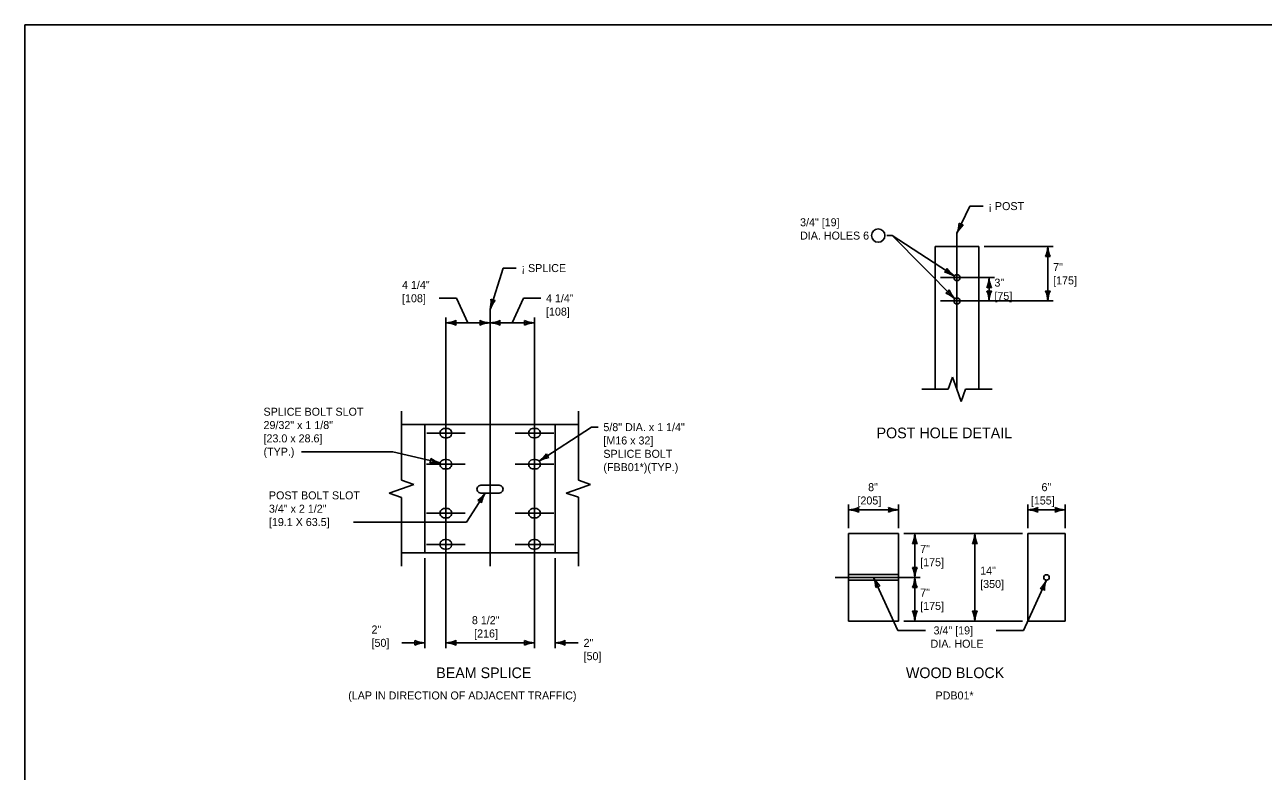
# Model space of a CAD drawing. Extents: x 49991.4 to 50021, y 49987.6 to 50011.4.
# Drawn here: x 49999.38 to 50008.67, y 49993.4 to 49999 of the extents above; entities that cross this region are included whole.
import ezdxf

# ---------------------------------------------------------------- set-up
doc = ezdxf.new("R2010")
doc.units = 0
for name, color, linetype in [('Level 1', 7, 'Continuous'), ('Level 2', 7, 'Continuous'), ('Level 3', 7, 'Continuous'), ('Level 4', 7, 'Continuous'), ('Level 5', 7, 'Continuous'), ('Level 6', 7, 'Continuous')]:
    doc.layers.add(name, color=color, linetype=linetype)

msp = doc.modelspace()

# ---------------------------------------------------------------- linework, layer by layer
at = {"layer": 'Level 1'}
for p, q in [((50006.209, 49997.3355), (50006.5371, 49997.3355)), ((50006.209, 49997.3355), (50006.209, 49996.2646)), ((50006.5371, 49997.3355), (50006.5371, 49996.2646)), ((50002.2084, 49995.9992), (50003.5353, 49995.9992)), ((50002.3835, 49995.0379), (50002.3835, 49995.9992)), ((50002.5496, 49995.9713), (50002.5326, 49995.9713)), ((50003.214, 49995.9714), (50003.197, 49995.9714)), ((50002.5496, 49995.9005), (50002.5326, 49995.9005)), ((50003.214, 49995.9006), (50003.197, 49995.9006)), ((50002.5495, 49995.7374), (50002.5325, 49995.7374)), ((50003.214, 49995.7374), (50003.197, 49995.7374)), ((50002.5495, 49995.6666), (50002.5325, 49995.6666)), ((50003.214, 49995.6666), (50003.197, 49995.6666)), ((50002.9403, 49995.5443), (50002.8036, 49995.5443)), ((50002.8036, 49995.4857), (50002.9403, 49995.4857)), ((50002.5495, 49995.3705), (50002.5325, 49995.3705)), ((50003.214, 49995.3705), (50003.197, 49995.3705)), ((50002.5495, 49995.2997), (50002.5325, 49995.2997)), ((50003.214, 49995.2997), (50003.197, 49995.2997)), ((50005.561, 49995.1822), (50005.9359, 49995.1822)), ((50005.561, 49995.1822), (50005.561, 49994.5256)), ((50005.9359, 49995.1822), (50005.9359, 49994.5256)), ((50006.9039, 49995.1822), (50006.9039, 49994.5256)), ((50006.9039, 49995.1822), (50007.1852, 49995.1822)), ((50007.1852, 49995.1822), (50007.1852, 49994.5256)), ((50002.5495, 49995.1366), (50002.5325, 49995.1366)), ((50003.214, 49995.1366), (50003.197, 49995.1366)), ((50002.2084, 49995.0379), (50003.5353, 49995.0379)), ((50002.5495, 49995.0658), (50002.5325, 49995.0658)), ((50003.214, 49995.0658), (50003.197, 49995.0658)), ((50005.561, 49994.5256), (50005.9359, 49994.5256)), ((50007.1852, 49994.5256), (50006.9039, 49994.5256))]:
    msp.add_line(p, q, dxfattribs=at)
msp.add_lwpolyline([(49999.3835, 49998.9992), (50016.7501, 49998.9992), (50016.7501, 49987.7988), (49999.3835, 49987.7988)], close=True, dxfattribs=at)
for centre, radius in [((50006.3731, 49997.1022), 0.0237), ((50006.3731, 49996.9272), 0.0237), ((50007.0448, 49994.8529), 0.0205)]:
    msp.add_circle(centre, radius, dxfattribs=at)
for centre, major_axis, ratio, start_param, end_param in [((50002.5326, 49995.9359), (0.0354, 0), 0.998676, 1.570796, 4.712389), ((50002.5496, 49995.9359), (0.0354, 0), 0.998676, 4.712389, 7.853982), ((50003.197, 49995.936), (0.0354, 0), 0.998676, 1.570796, 4.712389), ((50003.214, 49995.936), (0.0354, 0), 0.998676, 4.712389, 7.853982), ((50002.5325, 49995.702), (0.0354, 0), 0.998676, 1.570796, 4.712389), ((50002.5495, 49995.702), (0.0354, 0), 0.998676, 4.712389, 7.853982), ((50003.197, 49995.702), (0.0354, 0), 0.998676, 1.570796, 4.712389), ((50003.214, 49995.702), (0.0354, 0), 0.998676, 4.712389, 7.853982), ((50002.8036, 49995.515), (0.0296, 0), 0.988923, 1.570796, 4.712389), ((50002.9403, 49995.515), (0.0294, 0), 0.995211, 4.712389, 7.853982), ((50002.5325, 49995.3351), (0.0354, 0), 0.998676, 1.570796, 4.712389), ((50002.5495, 49995.3351), (0.0354, 0), 0.998676, 4.712389, 7.853982), ((50003.197, 49995.3351), (0.0354, 0), 0.998676, 1.570796, 4.712389), ((50003.214, 49995.3351), (0.0354, 0), 0.998676, 4.712389, 7.853982), ((50002.5325, 49995.1012), (0.0354, 0), 0.998676, 1.570796, 4.712389), ((50002.5495, 49995.1012), (0.0354, 0), 0.998676, 4.712389, 7.853982), ((50003.197, 49995.1012), (0.0354, 0), 0.998676, 1.570796, 4.712389), ((50003.214, 49995.1012), (0.0354, 0), 0.998676, 4.712389, 7.853982)]:
    msp.add_ellipse(centre, major_axis=major_axis, ratio=ratio, start_param=start_param, end_param=end_param, dxfattribs=at)
at = {"layer": 'Level 2'}
msp.add_circle((50005.7832, 49997.4175), 0.05, dxfattribs=at)
at = {"layer": 'Level 3'}
for p, q in [((50006.3731, 49997.4355), (50006.4709, 49997.6387)), ((50006.4709, 49997.6387), (50006.5692, 49997.6387)), ((50005.8467, 49997.4175), (50005.8867, 49997.4175)), ((50005.8867, 49997.4175), (50006.3564, 49996.944)), ((50005.8867, 49997.4175), (50006.3532, 49997.1151)), ((50006.5771, 49997.3355), (50007.0946, 49997.3355)), ((50007.0546, 49997.3355), (50007.0546, 49996.9272)), ((50002.872, 49996.8632), (50002.9698, 49997.1738)), ((50002.9698, 49997.1738), (50003.0681, 49997.1738)), ((50006.6143, 49997.1022), (50006.6143, 49996.9272)), ((50002.5411, 49996.7632), (50002.872, 49996.7632)), ((50003.2055, 49996.7632), (50002.872, 49996.7632)), ((50003.6342, 49995.9804), (50003.2409, 49995.725)), ((50003.6822, 49995.9804), (50003.6342, 49995.9804)), ((50002.143, 49995.7961), (50001.4574, 49995.7961)), ((50002.4985, 49995.7121), (50002.143, 49995.7961)), ((50002.6959, 49995.2685), (50002.835, 49995.4857)), ((50005.561, 49995.4002), (50005.561, 49995.2222)), ((50005.561, 49995.3602), (50005.9359, 49995.3602)), ((50005.9359, 49995.4002), (50005.9359, 49995.2222)), ((50006.9039, 49995.4002), (50006.9039, 49995.2222)), ((50006.9039, 49995.3602), (50007.1854, 49995.3602)), ((50007.1854, 49995.4002), (50007.1854, 49995.2222)), ((50001.848, 49995.2685), (50002.6959, 49995.2685)), ((50005.9759, 49995.1822), (50006.8639, 49995.1822)), ((50006.0577, 49995.1822), (50006.0577, 49994.8526)), ((50006.5075, 49995.1822), (50006.5075, 49994.5256)), ((50002.3835, 49994.9979), (50002.3835, 49994.3223)), ((50003.3602, 49994.9979), (50003.3602, 49994.3223)), ((50005.9289, 49994.4556), (50005.7484, 49994.8526)), ((50006.0577, 49994.8526), (50006.0577, 49994.5256)), ((50006.8735, 49994.4556), (50007.0448, 49994.8323)), ((50005.9759, 49994.5256), (50006.8639, 49994.5256)), ((50006.137, 49994.4556), (50005.9289, 49994.4556)), ((50006.6672, 49994.4556), (50006.8735, 49994.4556)), ((50002.2101, 49994.3623), (50002.3835, 49994.3623)), ((50002.5411, 49994.3623), (50003.2055, 49994.3623)), ((50003.5336, 49994.3623), (50003.3602, 49994.3623))]:
    msp.add_line(p, q, dxfattribs=at)
for points in [[(50002.7066, 49996.7632), (50002.6198, 49996.9472), (50002.492, 49996.9472)], [(50003.0375, 49996.7632), (50003.1242, 49996.9472), (50003.252, 49996.9472)]]:
    msp.add_lwpolyline(points, dxfattribs=at)
for centre, radius, start, end in [((50006.1573, 49997.5234), 0.233, 337.82731, 357.07716), ((50006.5705, 49997.3333), 0.2223, 132.45601, 152.63952), ((50006.4272, 49997.5517), 0.0548, 227.13882, 262.86118), ((50006.8324, 49997.3447), 0.2223, 337.45601, 357.63952), ((50007.2873, 49997.347), 0.233, 182.82731, 202.07716), ((50007.0546, 49997.2073), 0.0548, 72.13882, 107.86118), ((50006.2456, 49997.1849), 0.0548, 309.18565, 344.90801), ((50006.2362, 49996.9136), 0.233, 59.87414, 79.12399), ((50006.4817, 49997.2965), 0.2223, 214.50284, 234.68635), ((50006.3922, 49997.1114), 0.2223, 337.45601, 357.63952), ((50006.6143, 49996.974), 0.0548, 72.13882, 107.86118), ((50006.847, 49997.1137), 0.233, 182.82731, 202.07716), ((50002.6466, 49996.9221), 0.233, 345.34968, 4.59953), ((50002.9105, 49996.9855), 0.0548, 234.66119, 270.38355), ((50006.2661, 49997.035), 0.0548, 296.90501, 332.62737), ((50006.1992, 49996.772), 0.233, 47.5935, 66.84335), ((50006.5205, 49997.0939), 0.2223, 202.2222, 222.40571), ((50006.6143, 49997.0554), 0.0548, 252.13882, 287.86118), ((50006.3816, 49996.9157), 0.233, 2.82731, 22.07716), ((50006.8364, 49996.918), 0.2223, 157.45601, 177.63952), ((50007.0546, 49997.0554), 0.0548, 252.13882, 287.86118), ((50006.8218, 49996.9157), 0.233, 2.82731, 22.07716), ((50007.2767, 49996.918), 0.2223, 157.45601, 177.63952), ((50003.0811, 49996.7878), 0.2223, 139.97838, 160.16189), ((50002.5296, 49996.9959), 0.233, 272.82731, 292.07716), ((50002.5319, 49996.5411), 0.2223, 67.45601, 87.63952), ((50002.6693, 49996.7632), 0.0548, 162.13882, 197.86118), ((50002.8812, 49996.9853), 0.2223, 247.45601, 267.63952), ((50002.7438, 49996.7632), 0.0548, 342.13882, 17.86118), ((50002.8835, 49996.5305), 0.233, 92.82731, 112.07716), ((50002.8605, 49996.9959), 0.233, 272.82731, 292.07716), ((50002.8628, 49996.5411), 0.2223, 67.45601, 87.63952), ((50003.0002, 49996.7632), 0.0548, 162.13882, 197.86118), ((50003.2147, 49996.9853), 0.2223, 247.45601, 267.63952), ((50003.0773, 49996.7632), 0.0548, 342.13882, 17.86118), ((50003.217, 49996.5305), 0.233, 92.82731, 112.07716), ((50002.3737, 49995.7416), 0.0548, 328.83975, 4.56211), ((50002.5585, 49995.9261), 0.2223, 234.15694, 254.34045), ((50003.1043, 49995.9137), 0.233, 305.92164, 325.17149), ((50003.3546, 49995.5339), 0.2223, 100.55034, 120.73384), ((50003.3484, 49995.795), 0.0548, 195.23314, 230.95551), ((50002.4561, 49995.483), 0.233, 79.52824, 98.77809), ((50002.6529, 49995.6132), 0.2223, 304.81283, 324.99634), ((50003.0372, 49995.3699), 0.233, 150.18413, 169.43398), ((50002.7659, 49995.3777), 0.0548, 39.49564, 75.218), ((50005.5495, 49995.5929), 0.233, 272.82731, 292.07716), ((50005.5518, 49995.1381), 0.2223, 67.45601, 87.63952), ((50005.6892, 49995.3602), 0.0548, 162.13882, 197.86118), ((50005.945, 49995.5823), 0.2223, 247.45601, 267.63952), ((50005.8076, 49995.3602), 0.0548, 342.13882, 17.86118), ((50005.9474, 49995.1275), 0.233, 92.82731, 112.07716), ((50006.8924, 49995.5929), 0.233, 272.82731, 292.07716), ((50006.8947, 49995.1381), 0.2223, 67.45601, 87.63952), ((50007.0321, 49995.3602), 0.0548, 162.13882, 197.86118), ((50007.1945, 49995.5823), 0.2223, 247.45601, 267.63952), ((50007.0571, 49995.3602), 0.0548, 342.13882, 17.86118), ((50007.1969, 49995.1275), 0.233, 92.82731, 112.07716), ((50005.8355, 49995.1914), 0.2223, 337.45601, 357.63952), ((50006.2904, 49995.1937), 0.233, 182.82731, 202.07716), ((50006.2853, 49995.1914), 0.2223, 337.45601, 357.63952), ((50006.7402, 49995.1937), 0.233, 182.82731, 202.07716), ((50006.0577, 49995.054), 0.0548, 72.13882, 107.86118), ((50006.5075, 49995.054), 0.0548, 72.13882, 107.86118), ((50006.0577, 49994.9808), 0.0548, 252.13882, 287.86118), ((50005.8249, 49994.8411), 0.233, 2.82731, 22.07716), ((50006.2798, 49994.8434), 0.2223, 157.45601, 177.63952), ((50005.5424, 49994.769), 0.2223, 1.91578, 22.09929), ((50005.9554, 49994.9594), 0.233, 207.28708, 226.53693), ((50005.8355, 49994.8618), 0.2223, 337.45601, 357.63952), ((50006.2904, 49994.8641), 0.233, 182.82731, 202.07716), ((50006.8377, 49994.9391), 0.233, 313.46307, 332.71292), ((50007.2508, 49994.7487), 0.2223, 157.90071, 178.08422), ((50005.8015, 49994.7359), 0.0548, 96.59859, 132.32095), ((50006.0577, 49994.7244), 0.0548, 72.13882, 107.86118), ((50006.9917, 49994.7156), 0.0548, 47.67905, 83.40141), ((50006.0577, 49994.6538), 0.0548, 252.13882, 287.86118), ((50005.8249, 49994.5141), 0.233, 2.82731, 22.07716), ((50006.2798, 49994.5164), 0.2223, 157.45601, 177.63952), ((50006.5075, 49994.6538), 0.0548, 252.13882, 287.86118), ((50006.2747, 49994.5141), 0.233, 2.82731, 22.07716), ((50006.7296, 49994.5164), 0.2223, 157.45601, 177.63952), ((50002.3927, 49994.5844), 0.2223, 247.45601, 267.63952), ((50002.2553, 49994.3623), 0.0548, 342.13882, 17.86118), ((50002.395, 49994.1296), 0.233, 92.82731, 112.07716), ((50002.5296, 49994.595), 0.233, 272.82731, 292.07716), ((50002.5319, 49994.1402), 0.2223, 67.45601, 87.63952), ((50002.6693, 49994.3623), 0.0548, 162.13882, 197.86118), ((50003.2147, 49994.5845), 0.2223, 247.45601, 267.63952), ((50003.0773, 49994.3623), 0.0548, 342.13882, 17.86118), ((50003.217, 49994.1296), 0.233, 92.82731, 112.07716), ((50003.3487, 49994.595), 0.233, 272.82731, 292.07716), ((50003.351, 49994.1402), 0.2223, 67.45601, 87.63952), ((50003.4884, 49994.3623), 0.0548, 162.13882, 197.86118)]:
    msp.add_arc(centre, radius, start, end, dxfattribs=at)
at = {"layer": 'Level 4'}
for p, q in [((50003.3602, 49995.0379), (50003.3602, 49995.9992)), ((50005.9359, 49994.8743), (50005.561, 49994.8743)), ((50005.9359, 49994.8334), (50005.561, 49994.8334))]:
    msp.add_line(p, q, dxfattribs=at)
at = {"layer": 'Level 5'}
for p, q in [((50006.3731, 49996.2648), (50006.3731, 49997.4355)), ((50006.2493, 49997.1022), (50006.6543, 49997.1022)), ((50002.872, 49994.9379), (50002.872, 49996.8632)), ((50006.2493, 49996.9272), (50007.0946, 49996.9272)), ((50002.5411, 49994.3223), (50002.5411, 49996.8032)), ((50003.2055, 49994.3223), (50003.2055, 49996.8032)), ((50002.3971, 49995.936), (50002.6851, 49995.936)), ((50003.0615, 49995.936), (50003.3495, 49995.936)), ((50002.397, 49995.702), (50002.685, 49995.702)), ((50003.0615, 49995.702), (50003.3495, 49995.702)), ((50002.397, 49995.3351), (50002.685, 49995.3351)), ((50003.0615, 49995.3351), (50003.3495, 49995.3351)), ((50002.397, 49995.1012), (50002.685, 49995.1012)), ((50003.0615, 49995.1012), (50003.3495, 49995.1012)), ((50006.0977, 49994.8526), (50005.461, 49994.8526))]:
    msp.add_line(p, q, dxfattribs=at)
at = {"layer": 'Level 6'}
for p, q in [((50006.3083, 49996.2646), (50006.3407, 49996.356)), ((50006.3731, 49996.2646), (50006.3407, 49996.356)), ((50006.109, 49996.2646), (50006.3083, 49996.2646)), ((50006.4055, 49996.1732), (50006.3731, 49996.2646)), ((50006.4055, 49996.1732), (50006.4379, 49996.2646)), ((50006.4379, 49996.2646), (50006.6371, 49996.2646)), ((50002.2084, 49996.0992), (50002.2084, 49995.5834)), ((50003.5353, 49996.0992), (50003.5353, 49995.5836)), ((50002.2998, 49995.551), (50002.2084, 49995.5834)), ((50002.2998, 49995.551), (50002.2084, 49995.5186)), ((50003.6267, 49995.5512), (50003.5353, 49995.5836)), ((50003.6267, 49995.5512), (50003.5353, 49995.5188)), ((50002.2084, 49995.5186), (50002.117, 49995.4862)), ((50002.2084, 49995.4538), (50002.117, 49995.4862)), ((50002.2084, 49995.4538), (50002.2084, 49994.9379)), ((50003.5353, 49995.5188), (50003.4439, 49995.4864)), ((50003.5353, 49995.454), (50003.4439, 49995.4864)), ((50003.5353, 49995.454), (50003.5353, 49994.9379))]:
    msp.add_line(p, q, dxfattribs=at)

# ---------------------------------------------------------------- texts
at = {"layer": 'Level 2'}
for s, height, p in [('¡ POST', 0.06, (50006.6092, 49997.6087)), ('3/4" [19]', 0.06, (50005.1971, 49997.4875)), ('DIA. HOLES 6', 0.06, (50005.1971, 49997.3875)), ('7"', 0.06, (50007.0946, 49997.1513)), ('¡ SPLICE', 0.06, (50003.1081, 49997.1438)), ('4 1/4"', 0.06, (50002.2125, 49997.0172)), ('3"', 0.06, (50006.6543, 49997.0347)), ('[175]', 0.06, (50007.0946, 49997.0513)), ('[108]', 0.06, (50002.2125, 49996.9172)), ('4 1/4"', 0.06, (50003.292, 49996.9172)), ('[75]', 0.06, (50006.6543, 49996.9347)), ('[108]', 0.06, (50003.292, 49996.8172)), ('SPLICE BOLT SLOT', 0.06, (50001.1738, 49996.0661)), ('29/32" x 1 1/8"', 0.06, (50001.1738, 49995.9661)), ('5/8" DIA. x 1 1/4"', 0.06, (50003.7222, 49995.9504)), ('[23.0 x 28.6]', 0.06, (50001.1738, 49995.8661)), ('[M16 x 32]', 0.06, (50003.7222, 49995.8504)), ('POST HOLE DETAIL', 0.08, (50005.7706, 49995.8971)), ('(TYP.)', 0.06, (50001.1738, 49995.7661)), ('SPLICE BOLT ', 0.06, (50003.7222, 49995.7504)), ('(FBB01*)(TYP.) ', 0.06, (50003.7222, 49995.6504)), ('8"', 0.06, (50005.7072, 49995.5002)), ('6"', 0.06, (50007.0073, 49995.5002)), ('POST BOLT SLOT', 0.06, (50001.2144, 49995.4385)), ('[205]', 0.06, (50005.6273, 49995.4002)), ('[155]', 0.06, (50006.9275, 49995.4002)), ('3/4" x 2 1/2"', 0.06, (50001.2144, 49995.3385)), ('[19.1 X 63.5]', 0.06, (50001.2144, 49995.2385)), ('7"', 0.06, (50006.0977, 49995.0374)), ('[175]', 0.06, (50006.0977, 49994.9374)), ('14"', 0.06, (50006.5475, 49994.8739)), ('[350]', 0.06, (50006.5475, 49994.7739)), ('7"', 0.06, (50006.0977, 49994.7091)), ('[175]', 0.06, (50006.0977, 49994.6091)), ('8 1/2"', 0.06, (50002.7362, 49994.5023)), ('2"', 0.06, (50001.9835, 49994.4323)), ('[216]', 0.06, (50002.7531, 49994.4023)), ('3/4" [19]', 0.06, (50006.1978, 49994.4256)), ('[50]', 0.06, (50001.9835, 49994.3323)), ('2"', 0.06, (50003.5736, 49994.3323)), ('DIA. HOLE', 0.06, (50006.1757, 49994.3256)), ('[50]', 0.06, (50003.5736, 49994.2323)), ('BEAM SPLICE', 0.08, (50002.4687, 49994.0975)), ('WOOD BLOCK', 0.08, (50005.9906, 49994.0975)), ('(LAP IN DIRECTION OF ADJACENT TRAFFIC)', 0.06, (50001.8088, 49993.9375)), ('PDB01*', 0.06, (50006.2127, 49993.9375))]:
    msp.add_text(s, height=height, dxfattribs=at).set_placement(p)

doc.saveas('drawing.dxf')
